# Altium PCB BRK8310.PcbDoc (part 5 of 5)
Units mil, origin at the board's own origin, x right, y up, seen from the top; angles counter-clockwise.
Board outline 6600.39 x 4492.13 mil, 4 copper layers (L1-Top, L2-GND, L3-GND, L4-BOT), stack 60.25 mil thick; 119 components, 266 nets, 1026 pads, 596 vias.
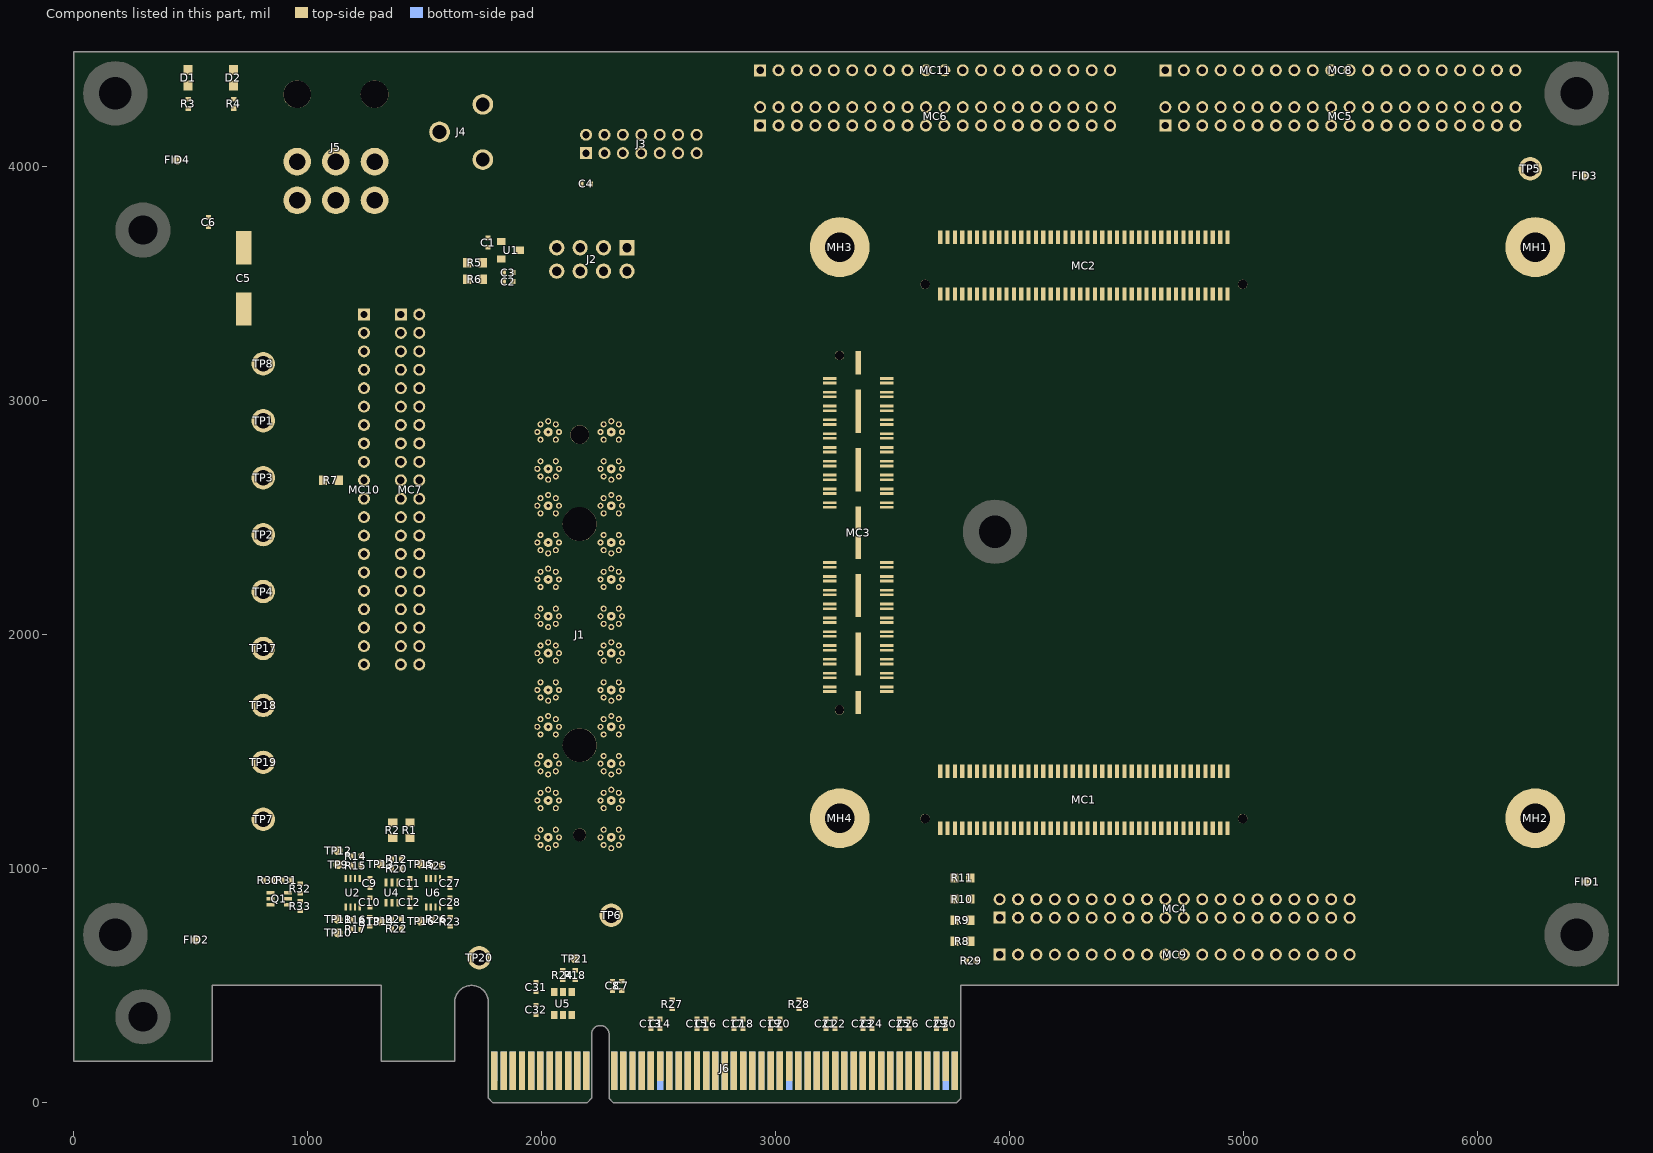
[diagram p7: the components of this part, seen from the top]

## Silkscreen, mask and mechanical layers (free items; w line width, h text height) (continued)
Outline:
  lines w3.94: -0.01,177.16 -0.01,4492.13 6600.39,4492.13 6600.39,501.97 3791.33,501.97 3791.33,19.68 3771.65,0 2307.08,0 2287.39,19.68 2287.39,293.31 ccw(c2249.99,293.31) 2212.59,293.31 2212.59,19.68 2192.91,0 1791.33,0 1771.65,19.68 1771.65,430.12 ccw(c1699.8,430.12) 1627.94,430.12 1627.94,177.16 1312.98,177.16 1312.98,501.97 590.54,501.97 590.54,177.16 -0.01,177.16
  lines w11.81: 6600.39,1059.05 6600.39,3814.96
Fab Notes:
  drawing of 62 lines, arcs and shapes, not listed
  text "LAYER STACKUP TABLE" at 7937.01,7409.45 h80
  text "S" at 12634.42,7288.77 h81.74
  text "i" at 12667.19,7288.77 h81.74
  text "n" at 12685.92,7288.77 h81.74
  text "g" at 12723.37,7288.77 h81.74
  text "l" at 12756.14,7288.77 h81.74
  text "e" at 12774.86,7288.77 h81.74
  text "-" at 12812.31,7288.76 h81.74
  text "D" at 10924.29,7195.14 h81.74
  text "i" at 10966.42,7195.14 h81.74
  text "f" at 10985.14,7195.14 h81.74
  text "f" at 11008.55,7195.14 h81.74
  text "e" at 11031.96,7195.14 h81.74
  text "r" at 11069.41,7195.14 h81.74
  text "e" at 11092.81,7195.14 h81.74
  text "n" at 11130.26,7195.14 h81.74
  text "t" at 11167.71,7195.14 h81.74
  text "i" at 11191.12,7195.14 h81.74
  text "a" at 11209.85,7195.14 h81.74
  text "l" at 11242.62,7195.14 h81.74
  text "D" at 11312.1,7195.14 h81.74
  text "i" at 11354.24,7195.14 h81.74
  text "f" at 11372.96,7195.14 h81.74
  text "f" at 11396.37,7195.14 h81.74
  text "e" at 11419.77,7195.14 h81.74
  text "r" at 11457.22,7195.14 h81.74
  text "e" at 11480.63,7195.14 h81.74
  text "n" at 11518.08,7195.14 h81.74
  text "t" at 11555.53,7195.14 h81.74
  text "i" at 11578.94,7195.14 h81.74
  text "a" at 11597.66,7195.14 h81.74
  text "l" at 11630.43,7195.14 h81.74
  text "D" at 11746.65,7195.14 h81.74
  text "i" at 11788.78,7195.14 h81.74
  text "f" at 11807.5,7195.14 h81.74
  text "f" at 11830.91,7195.14 h81.74
  text "e" at 11854.32,7195.14 h81.74
  text "r" at 11891.77,7195.14 h81.74
  text "e" at 11915.17,7195.14 h81.74
  text "n" at 11952.62,7195.14 h81.74
  text "t" at 11990.07,7195.14 h81.74
  text "i" at 12013.48,7195.14 h81.74
  text "a" at 12032.21,7195.14 h81.74
  text "l" at 12064.98,7195.14 h81.74
  text "D" at 12134.46,7195.14 h81.74
  text "i" at 12176.6,7195.14 h81.74
  text "f" at 12195.32,7195.14 h81.74
  text "f" at 12218.73,7195.14 h81.74
  text "e" at 12242.13,7195.14 h81.74
  text "r" at 12279.58,7195.14 h81.74
  text "e" at 12302.99,7195.14 h81.74
  text "n" at 12340.44,7195.14 h81.74
  text "t" at 12377.89,7195.14 h81.74
  text "i" at 12401.3,7195.14 h81.74
  text "a" at 12420.02,7195.14 h81.74
  text "l" at 12452.79,7195.14 h81.74
  text "E" at 12643.77,7195.14 h81.74
  text "n" at 12676.54,7195.14 h81.74
  text "d" at 12713.99,7195.14 h81.74
  text "e" at 12751.44,7195.14 h81.74
  text "d" at 12788.89,7195.14 h81.74
  text "T" at 11017.74,7101.52 h81.74
  text "r" at 11050.51,7101.52 h81.74
  text "a" at 11073.91,7101.52 h81.74
  text "c" at 11106.68,7101.52 h81.74
  text "e" at 11134.77,7101.52 h81.74
  text "T" at 11405.55,7101.52 h81.74
  text "r" at 11438.32,7101.52 h81.74
  text "a" at 11461.73,7101.52 h81.74
  text "c" at 11494.5,7101.52 h81.74
  text "e" at 11522.59,7101.52 h81.74
  text "T" at 11840.1,7101.52 h81.74
  text "r" at 11872.87,7101.52 h81.74
  text "a" at 11896.27,7101.52 h81.74
  text "c" at 11929.04,7101.52 h81.74
  text "e" at 11957.13,7101.52 h81.74
  text "T" at 12227.91,7101.52 h81.74
  text "r" at 12260.68,7101.52 h81.74
  text "a" at 12284.09,7101.52 h81.74
  text "c" at 12316.86,7101.52 h81.74
  text "e" at 12344.95,7101.52 h81.74
  text "T" at 12657.78,7101.52 h81.74
  text "r" at 12690.55,7101.52 h81.74
  text "a" at 12713.96,7101.52 h81.74
  text "c" at 12746.73,7101.52 h81.74
  text "e" at 12774.82,7101.52 h81.74
  text "S" at 12933.46,7101.52 h81.74
  text "i" at 12966.23,7101.52 h81.74
  text "n" at 12984.96,7101.52 h81.74
  text "g" at 13022.41,7101.52 h81.74
  text "l" at 13055.18,7101.52 h81.74
  text "e" at 13073.9,7101.52 h81.74
  text "-" at 13111.35,7101.51 h81.74
  text "E" at 13134.76,7101.51 h81.74
  text "n" at 13167.53,7101.52 h81.74
  text "d" at 13204.98,7101.52 h81.74
  text "e" at 13242.43,7101.52 h81.74
  text "d" at 13279.88,7101.52 h81.74
  text "M" at 10120.62,7100.13 h77.19
  text "a" at 10172.11,7100.13 h77.19
  text "t" at 10209.56,7100.13 h77.19
  text "e" at 10228.29,7100.13 h77.19
  text "r" at 10265.74,7100.13 h77.19
  text "i" at 10289.14,7100.13 h77.19
  text "a" at 10303.19,7100.13 h77.19
  text "l" at 10340.64,7100.13 h77.19
  text "G" at 8816.99,7011.19 h77.19
  text "e" at 8868.48,7011.19 h77.19
  text "r" at 8905.93,7011.19 h77.19
  text "b" at 8929.34,7011.19 h77.19
  text "e" at 8966.79,7011.19 h77.19
  text "r" at 9004.24,7011.19 h77.19
  text "M" at 9578.61,7011.19 h77.19
  text "a" at 9630.1,7011.19 h77.19
  text "t" at 9667.55,7011.19 h77.19
  text "e" at 9686.28,7011.19 h77.19
  text "r" at 9723.73,7011.19 h77.19
  text "i" at 9747.13,7011.19 h77.19
  text "a" at 9761.18,7011.19 h77.19
  text "l" at 9798.63,7011.19 h77.19
  text "T" at 10078.56,7011.19 h77.19
  text "h" at 10120.7,7011.19 h77.19
  text "i" at 10158.15,7011.19 h77.19
  text "c" at 10172.19,7011.19 h77.19
  text "k" at 10209.64,7011.19 h77.19
  text "n" at 10242.41,7011.19 h77.19
  text "e" at 10279.86,7011.19 h77.19
  text "s" at 10317.31,7011.19 h77.19
  text "s" at 10354.76,7011.19 h77.19
  text "C" at 10541.14,7007.89 h81.74
  text "o" at 10578.59,7007.89 h81.74
  text "p" at 10616.04,7007.89 h81.74
  text "p" at 10653.49,7007.89 h81.74
  text "e" at 10690.94,7007.89 h81.74
  text "r" at 10728.39,7007.89 h81.74
  text "I" at 10933.63,7007.89 h81.74
  text "m" at 10952.36,7007.89 h81.74
  text "p" at 11008.53,7007.89 h81.74
  text "e" at 11045.98,7007.89 h81.74
  text "d" at 11083.43,7007.89 h81.74
  text "a" at 11120.88,7007.89 h81.74
  text "n" at 11153.65,7007.89 h81.74
  text "c" at 11191.1,7007.89 h81.74
  text "e" at 11219.19,7007.89 h81.74
  text "W" at 11293.41,7007.89 h81.74
  text "i" at 11354.27,7007.89 h81.74
  text "d" at 11373,7007.89 h81.74
  text "t" at 11410.45,7007.89 h81.74
  text "h" at 11433.85,7007.89 h81.74
  text "/" at 11471.3,7007.89 h81.74
  text "S" at 11499.39,7007.89 h81.74
  text "p" at 11532.16,7007.89 h81.74
  text "a" at 11569.61,7007.89 h81.74
  text "c" at 11602.38,7007.89 h81.74
  text "e" at 11630.47,7007.89 h81.74
  text "I" at 11755.99,7007.89 h81.74
  text "m" at 11774.72,7007.89 h81.74
  text "p" at 11830.89,7007.89 h81.74
  text "e" at 11868.34,7007.89 h81.74
  text "d" at 11905.79,7007.89 h81.74
  text "a" at 11943.24,7007.89 h81.74
  text "n" at 11976.01,7007.89 h81.74
  text "c" at 12013.46,7007.89 h81.74
  text "e" at 12041.55,7007.89 h81.74
  text "W" at 12115.77,7007.89 h81.74
  text "i" at 12176.63,7007.89 h81.74
  text "d" at 12195.36,7007.89 h81.74
  text "t" at 12232.81,7007.89 h81.74
  text "h" at 12256.21,7007.89 h81.74
  text "/" at 12293.66,7007.89 h81.74
  text "S" at 12321.75,7007.89 h81.74
  text "p" at 12354.52,7007.89 h81.74
  text "a" at 12391.97,7007.89 h81.74
  text "c" at 12424.74,7007.89 h81.74
  text "e" at 12452.83,7007.89 h81.74
  text "I" at 12573.68,7007.89 h81.74
  text "m" at 12592.4,7007.89 h81.74
  text "p" at 12648.58,7007.89 h81.74
  text "e" at 12686.03,7007.89 h81.74
  text "d" at 12723.48,7007.89 h81.74
  text "a" at 12760.93,7007.89 h81.74
  text "n" at 12793.7,7007.89 h81.74
  text "c" at 12831.15,7007.89 h81.74
  text "e" at 12859.24,7007.89 h81.74
  text "T" at 12952.15,7007.89 h81.74
  text "r" at 12984.92,7007.89 h81.74
  text "a" at 13008.33,7007.89 h81.74
  text "c" at 13041.1,7007.89 h81.74
  text "e" at 13069.18,7007.89 h81.74
  text "W" at 13120.68,7007.89 h81.74
  text "i" at 13181.54,7007.89 h81.74
  text "d" at 13200.26,7007.89 h81.74
  text "t" at 13237.71,7007.89 h81.74
  text "h" at 13261.12,7007.89 h81.74
  text "L" at 7919.87,6922.24 h77.19
  text "a" at 7957.32,6922.24 h77.19
  text "y" at 7994.77,6922.23 h77.19
  text "e" at 8027.54,6922.24 h77.19
  text "r" at 8064.99,6922.24 h77.19
  text "L" at 8153.49,6922.24 h77.19
  text "a" at 8190.94,6922.24 h77.19
  text "y" at 8228.4,6922.23 h77.19
  text "e" at 8261.16,6922.24 h77.19
  text "r" at 8298.61,6922.24 h77.19
  text "N" at 8340.75,6922.24 h77.19
  text "a" at 8387.56,6922.24 h77.19
  text "m" at 8425.01,6922.24 h77.19
  text "e" at 8485.87,6922.24 h77.19
  text "L" at 8816.99,6922.24 h77.19
  text "a" at 8854.44,6922.24 h77.19
  text "y" at 8891.89,6922.23 h77.19
  text "e" at 8924.66,6922.24 h77.19
  text "r" at 8962.11,6922.24 h77.19
  text "M" at 9097.34,6922.24 h77.19
  text "a" at 9148.83,6922.24 h77.19
  text "t" at 9186.28,6922.24 h77.19
  text "e" at 9205.01,6922.24 h77.19
  text "r" at 9242.46,6922.24 h77.19
  text "i" at 9265.87,6922.24 h77.19
  text "a" at 9279.91,6922.24 h77.19
  text "l" at 9317.36,6922.24 h77.19
  text "T" at 9350.13,6922.24 h77.19
  text "y" at 9392.26,6922.23 h77.19
  text "p" at 9425.03,6922.24 h77.19
  text "e" at 9462.48,6922.24 h77.19
  text "C" at 9578.61,6922.24 h77.19
  text "o" at 9630.1,6922.24 h77.19
  text "n" at 9667.55,6922.24 h77.19
  text "s" at 9705,6922.24 h77.19
  text "t" at 9742.45,6922.24 h77.19
  text "r" at 9761.18,6922.24 h77.19
  text "u" at 9784.58,6922.24 h77.19
  text "c" at 9822.03,6922.24 h77.19
  text "t" at 9859.48,6922.24 h77.19
  text "i" at 9878.21,6922.24 h77.19
  text "o" at 9892.25,6922.24 h77.19
  text "n" at 9929.7,6922.24 h77.19
  text "(" at 10153.32,6922.23 h77.19
  text "m" at 10176.73,6922.24 h77.19
  text "m" at 10237.59,6922.24 h77.19
  text ")" at 10298.44,6922.23 h77.19
  text "W" at 10475.73,6914.26 h81.74
  text "e" at 10536.58,6914.26 h81.74
  text "i" at 10574.03,6914.26 h81.74
  text "g" at 10592.76,6914.27 h81.74
  text "h" at 10625.53,6914.26 h81.74
  text "t" at 10662.98,6914.26 h81.74
  text "(" at 10700.43,6914.27 h81.74
  text "o" at 10723.84,6914.26 h81.74
  text "z" at 10761.29,6914.26 h81.74
  text ")" at 10789.37,6914.27 h81.74
  text "(" at 10989.7,6914.27 h81.74
  text "o" at 11013.11,6914.26 h81.74
  text "h" at 11050.56,6914.26 h81.74
  text "m" at 11088.01,6914.26 h81.74
  text "s" at 11144.18,6914.26 h81.74
  text ")" at 11172.27,6914.27 h81.74
  text "(" at 11396.21,6914.27 h81.74
  text "m" at 11419.62,6914.26 h81.74
  text "i" at 11475.79,6914.26 h81.74
  text "l" at 11494.52,6914.26 h81.74
  text "s" at 11513.24,6914.26 h81.74
  text ")" at 11541.33,6914.27 h81.74
  text "(" at 11812.06,6914.27 h81.74
  text "o" at 11835.47,6914.26 h81.74
  text "h" at 11872.92,6914.26 h81.74
  text "m" at 11910.37,6914.26 h81.74
  text "s" at 11966.54,6914.26 h81.74
  text ")" at 11994.63,6914.27 h81.74
  text "(" at 12218.57,6914.27 h81.74
  text "m" at 12241.98,6914.26 h81.74
  text "i" at 12298.15,6914.26 h81.74
  text "l" at 12316.88,6914.26 h81.74
  text "s" at 12335.6,6914.26 h81.74
  text ")" at 12363.69,6914.27 h81.74
  text "(" at 12634.42,6914.27 h81.74
  text "o" at 12657.83,6914.26 h81.74
  text "h" at 12695.28,6914.26 h81.74
  text "m" at 12732.73,6914.26 h81.74
  text "s" at 12788.9,6914.26 h81.74
  text ")" at 12816.99,6914.27 h81.74
  text "(" at 13040.93,6914.27 h81.74
  text "m" at 13064.34,6914.26 h81.74
  text "i" at 13120.51,6914.26 h81.74
  text "l" at 13139.24,6914.26 h81.74
  text "s" at 13157.96,6914.26 h81.74
  text ")" at 13186.05,6914.27 h81.74
  text "O" at 8153.49,6781.81 h77.19
  text "v" at 8209.67,6781.81 h77.19
  text "e" at 8242.44,6781.81 h77.19
  text "r" at 8279.89,6781.81 h77.19
  text "l" at 8303.3,6781.81 h77.19
  text "a" at 8317.34,6781.81 h77.19
  text "y" at 8354.79,6781.8 h77.19
  text "T" at 8406.28,6781.81 h77.19
  text "o" at 8448.42,6781.81 h77.19
  text "p" at 8485.87,6781.8 h77.19
  text "G" at 8816.99,6781.81 h77.19
  text "T" at 8868.48,6781.81 h77.19
  text "O" at 8910.62,6781.81 h77.19
  text "S" at 9097.34,6781.81 h77.19
  text "i" at 9144.15,6781.81 h77.19
  text "l" at 9158.2,6781.81 h77.19
  text "k" at 9172.24,6781.81 h77.19
  text "s" at 9205.01,6781.81 h77.19
  text "c" at 9242.46,6781.81 h77.19
  text "r" at 9279.91,6781.81 h77.19
  text "e" at 9303.32,6781.81 h77.19
  text "e" at 9340.77,6781.81 h77.19
  text "n" at 9378.22,6781.81 h77.19
  text "S" at 8153.49,6688.18 h77.19
  text "o" at 8200.31,6688.18 h77.19
  text "l" at 8237.76,6688.18 h77.19
  text "d" at 8251.8,6688.18 h77.19
  text "e" at 8289.25,6688.18 h77.19
  text "r" at 8326.7,6688.18 h77.19
  text "M" at 8368.83,6688.18 h77.19
  text "a" at 8420.33,6688.18 h77.19
  text "s" at 8457.78,6688.18 h77.19
  text "k" at 8495.23,6688.18 h77.19
  text "T" at 8546.72,6688.18 h77.19
  text "o" at 8588.86,6688.18 h77.19
  text "p" at 8626.31,6688.17 h77.19
  text "G" at 8816.99,6688.18 h77.19
  text "T" at 8868.48,6688.18 h77.19
  text "S" at 8910.62,6688.18 h77.19
  text "S" at 9097.34,6688.18 h77.19
  text "o" at 9144.15,6688.18 h77.19
  text "l" at 9181.6,6688.18 h77.19
  text "d" at 9195.65,6688.18 h77.19
  text "e" at 9233.1,6688.18 h77.19
  text "r" at 9270.55,6688.18 h77.19
  text "R" at 9312.68,6688.18 h77.19
  text "e" at 9364.17,6688.18 h77.19
  text "s" at 9401.62,6688.18 h77.19
  text "i" at 9439.07,6688.18 h77.19
  text "s" at 9453.12,6688.18 h77.19
  text "t" at 9490.57,6688.18 h77.19
  text "1" at 7919.87,6594.55 h77.19
  text "L" at 8153.49,6594.55 h77.19
  text "1" at 8190.94,6594.55 h77.19
  text "-" at 8228.4,6594.56 h77.19
  text "T" at 8251.8,6594.55 h77.19
  text "O" at 8293.93,6594.55 h77.19
  text "P" at 8350.11,6594.55 h77.19
  text "G" at 8816.99,6594.55 h77.19
  text "T" at 8868.48,6594.55 h77.19
  text "L" at 8910.62,6594.55 h77.19
  text "C" at 9097.34,6594.55 h77.19
  text "o" at 9148.83,6594.55 h77.19
  text "p" at 9186.28,6594.54 h77.19
  text "p" at 9223.73,6594.54 h77.19
  text "e" at 9261.18,6594.55 h77.19
  text "r" at 9298.64,6594.55 h77.19
  text "0" at 10471.05,6591.25 h81.74
  text "." at 10503.82,6591.25 h81.74
  text "5" at 10522.55,6591.25 h81.74
  text "+" at 10569.36,6591.25 h81.74
  text "p" at 10616.17,6591.26 h81.74
  text "l" at 10653.62,6591.25 h81.74
  text "a" at 10672.35,6591.25 h81.74
  text "t" at 10705.12,6591.25 h81.74
  text "i" at 10728.53,6591.25 h81.74
  text "n" at 10747.25,6591.25 h81.74
  text "g" at 10784.7,6591.26 h81.74
  text "8" at 11059.79,6591.25 h81.74
  text "5" at 11092.56,6591.25 h81.74
  text "7" at 11335.47,6591.25 h81.74
  text "." at 11368.24,6591.25 h81.74
  text "5" at 11386.96,6591.25 h81.74
  text "0" at 11419.73,6591.25 h81.74
  text "/" at 11466.54,6591.26 h81.74
  text "6" at 11508.67,6591.25 h81.74
  text "." at 11541.44,6591.25 h81.74
  text "0" at 11560.17,6591.25 h81.74
  text "0" at 11592.94,6591.25 h81.74
  text "1" at 11868.13,6591.25 h81.74
  text "0" at 11900.9,6591.25 h81.74
  text "0" at 11933.67,6591.25 h81.74
  text "5" at 12157.83,6591.25 h81.74
  text "." at 12190.6,6591.25 h81.74
  text "2" at 12209.32,6591.25 h81.74
  text "5" at 12242.09,6591.25 h81.74
  text "/" at 12288.9,6591.26 h81.74
  text "6" at 12331.03,6591.25 h81.74
  text "." at 12363.8,6591.25 h81.74
  text "0" at 12382.53,6591.25 h81.74
  text "0" at 12415.3,6591.25 h81.74
  text "5" at 12704.51,6591.25 h81.74
  text "0" at 12737.28,6591.25 h81.74
  text "7" at 13082.98,6591.25 h81.74
  text "." at 13115.75,6591.25 h81.74
  text "5" at 13134.48,6591.25 h81.74
  text "P" at 9097.34,6500.93 h77.19
  text "r" at 9144.15,6500.93 h77.19
  text "e" at 9167.56,6500.93 h77.19
  text "p" at 9205.01,6500.92 h77.19
  text "r" at 9242.46,6500.93 h77.19
  text "e" at 9265.87,6500.93 h77.19
  text "g" at 9303.32,6500.92 h77.19
  text "S" at 9578.61,6497.63 h81.74
  text "1" at 9611.38,6497.63 h81.74
  text "0" at 9644.15,6497.63 h81.74
  text "0" at 9676.91,6497.63 h81.74
  text "0" at 9709.68,6497.63 h81.74
  text "-" at 9742.45,6497.62 h81.74
  text "2" at 9765.86,6497.63 h81.74
  text "M" at 9798.63,6497.63 h81.74
  text "0" at 10162.67,6497.63 h81.74
  text "." at 10195.44,6497.63 h81.74
  text "1" at 10214.16,6497.63 h81.74
  text "2" at 10246.93,6497.63 h81.74
  text "3" at 10279.7,6497.63 h81.74
  text "2" at 7919.87,6407.3 h77.19
  text "L" at 8153.49,6407.3 h77.19
  text "2" at 8190.94,6407.3 h77.19
  text "-" at 8228.4,6407.31 h77.19
  text "G" at 8251.8,6407.3 h77.19
  text "N" at 8303.3,6407.3 h77.19
  text "D" at 8350.11,6407.3 h77.19
  text "G" at 8816.99,6407.3 h77.19
  text "1" at 8868.48,6407.3 h77.19
  text "C" at 9097.34,6407.3 h77.19
  text "o" at 9148.83,6407.3 h77.19
  text "p" at 9186.28,6407.29 h77.19
  text "p" at 9223.73,6407.29 h77.19
  text "e" at 9261.18,6407.3 h77.19
  text "r" at 9298.64,6407.3 h77.19
  text "1" at 10629.92,6404 h81.74
  text "C" at 9097.34,6313.68 h77.19
  text "o" at 9148.83,6313.68 h77.19
  text "r" at 9186.28,6313.68 h77.19
  text "e" at 9209.69,6313.68 h77.19
  text "1" at 10162.67,6310.38 h81.74
  text "." at 10195.44,6310.38 h81.74
  text "1" at 10214.16,6310.38 h81.74
  text "4" at 10246.93,6310.38 h81.74
  text "3" at 10279.7,6310.38 h81.74
  text "3" at 7919.87,6220.05 h77.19
  text "L" at 8153.49,6220.05 h77.19
  text "3" at 8190.94,6220.05 h77.19
  text "-" at 8228.4,6220.06 h77.19
  text "P" at 8251.8,6220.05 h77.19
  text "W" at 8298.61,6220.05 h77.19
  text "R" at 8368.83,6220.05 h77.19
  text "G" at 8816.99,6220.05 h77.19
  text "2" at 8868.48,6220.05 h77.19
  text "C" at 9097.34,6220.05 h77.19
  text "o" at 9148.83,6220.05 h77.19
  text "p" at 9186.28,6220.04 h77.19
  text "p" at 9223.73,6220.04 h77.19
  text "e" at 9261.18,6220.05 h77.19
  text "r" at 9298.64,6220.05 h77.19
  text "1" at 10629.92,6216.75 h81.74
  text "P" at 9097.34,6126.42 h77.19
  text "r" at 9144.15,6126.42 h77.19
  text "e" at 9167.56,6126.42 h77.19
  text "p" at 9205.01,6126.41 h77.19
  text "r" at 9242.46,6126.42 h77.19
  text "e" at 9265.87,6126.42 h77.19
  text "g" at 9303.32,6126.41 h77.19
  text "S" at 9578.61,6123.12 h81.74
  text "1" at 9611.38,6123.12 h81.74
  text "0" at 9644.15,6123.12 h81.74
  text "0" at 9676.91,6123.12 h81.74
  text "0" at 9709.68,6123.12 h81.74
  text "-" at 9742.45,6123.12 h81.74
  text "2" at 9765.86,6123.12 h81.74
  text "M" at 9798.63,6123.12 h81.74
  text "0" at 10162.67,6123.12 h81.74
  text "." at 10195.44,6123.12 h81.74
  text "1" at 10214.16,6123.12 h81.74
  text "2" at 10246.93,6123.12 h81.74
  text "3" at 10279.7,6123.12 h81.74
  text "4" at 7919.87,6032.8 h77.19
  text "L" at 8153.49,6032.8 h77.19
  text "4" at 8190.94,6032.8 h77.19
  text "-" at 8228.4,6032.81 h77.19
  text "B" at 8251.8,6032.8 h77.19
  text "O" at 8298.61,6032.8 h77.19
  text "T" at 8354.79,6032.8 h77.19
  text "G" at 8816.99,6032.8 h77.19
  text "B" at 8868.48,6032.8 h77.19
  text "L" at 8915.3,6032.8 h77.19
  text "C" at 9097.34,6032.8 h77.19
  text "o" at 9148.83,6032.8 h77.19
  text "p" at 9186.28,6032.79 h77.19
  text "p" at 9223.73,6032.79 h77.19
  text "e" at 9261.18,6032.8 h77.19
  text "r" at 9298.64,6032.8 h77.19
  text "p" at 10616.17,6029.5 h81.74
  text "g" at 10784.7,6029.5 h81.74
  text "/" at 11466.54,6029.5 h81.74
  text "/" at 12288.9,6029.5 h81.74
  text "0" at 10471.05,6029.5 h81.74
  text "." at 10503.82,6029.5 h81.74
  text "5" at 10522.55,6029.5 h81.74
  text "+" at 10569.36,6029.5 h81.74
  text "l" at 10653.62,6029.5 h81.74
  text "a" at 10672.35,6029.5 h81.74
  text "t" at 10705.12,6029.5 h81.74
  text "i" at 10728.53,6029.5 h81.74
  text "n" at 10747.25,6029.5 h81.74
  text "8" at 11059.79,6029.5 h81.74
  text "5" at 11092.56,6029.5 h81.74
  text "7" at 11335.47,6029.5 h81.74
  text "." at 11368.24,6029.5 h81.74
  text "5" at 11386.96,6029.5 h81.74
  text "0" at 11419.73,6029.5 h81.74
  text "6" at 11508.67,6029.5 h81.74
  text "." at 11541.44,6029.5 h81.74
  text "0" at 11560.17,6029.5 h81.74
  text "0" at 11592.94,6029.5 h81.74
  text "1" at 11868.13,6029.5 h81.74
  text "0" at 11900.9,6029.5 h81.74
  text "0" at 11933.67,6029.5 h81.74
  text "5" at 12157.83,6029.5 h81.74
  text "." at 12190.6,6029.5 h81.74
  text "2" at 12209.32,6029.5 h81.74
  text "5" at 12242.09,6029.5 h81.74
  text "6" at 12331.03,6029.5 h81.74
  text "." at 12363.8,6029.5 h81.74
  text "0" at 12382.53,6029.5 h81.74
  text "0" at 12415.3,6029.5 h81.74
  text "5" at 12704.51,6029.5 h81.74
  text "0" at 12737.28,6029.5 h81.74
  text "7" at 13082.98,6029.5 h81.74
  text "." at 13115.75,6029.5 h81.74
  text "5" at 13134.48,6029.5 h81.74
  text "S" at 8153.49,5939.17 h77.19
  text "o" at 8200.31,5939.17 h77.19
  text "l" at 8237.76,5939.17 h77.19
  text "d" at 8251.8,5939.17 h77.19
  text "e" at 8289.25,5939.17 h77.19
  text "r" at 8326.7,5939.17 h77.19
  text "M" at 8368.83,5939.17 h77.19
  text "a" at 8420.33,5939.17 h77.19
  text "s" at 8457.78,5939.17 h77.19
  text "k" at 8495.23,5939.17 h77.19
  text "B" at 8546.72,5939.17 h77.19
  text "o" at 8593.54,5939.17 h77.19
  text "t" at 8630.99,5939.17 h77.19
  text "t" at 8649.71,5939.17 h77.19
  text "o" at 8668.44,5939.17 h77.19
  text "m" at 8705.89,5939.17 h77.19
  text "G" at 8816.99,5939.17 h77.19
  text "B" at 8868.48,5939.17 h77.19
  text "S" at 8915.3,5939.17 h77.19
  text "S" at 9097.34,5939.17 h77.19
  text "o" at 9144.15,5939.17 h77.19
  text "l" at 9181.6,5939.17 h77.19
  text "d" at 9195.65,5939.17 h77.19
  text "e" at 9233.1,5939.17 h77.19
  text "r" at 9270.55,5939.17 h77.19
  text "R" at 9312.68,5939.17 h77.19
  text "e" at 9364.17,5939.17 h77.19
  text "s" at 9401.62,5939.17 h77.19
  text "i" at 9439.07,5939.17 h77.19
  text "s" at 9453.12,5939.17 h77.19
  text "t" at 9490.57,5939.17 h77.19
  text "O" at 8153.49,5845.55 h77.19
  text "v" at 8209.67,5845.55 h77.19
  text "e" at 8242.44,5845.55 h77.19
  text "r" at 8279.89,5845.55 h77.19
  text "l" at 8303.3,5845.55 h77.19
  text "a" at 8317.34,5845.55 h77.19
  text "y" at 8354.79,5845.54 h77.19
  text "B" at 8406.28,5845.55 h77.19
  text "o" at 8453.1,5845.55 h77.19
  text "t" at 8490.55,5845.55 h77.19
  text "t" at 8509.27,5845.55 h77.19
  text "o" at 8528,5845.55 h77.19
  text "m" at 8565.45,5845.55 h77.19
  text "G" at 8816.99,5845.55 h77.19
  text "B" at 8868.48,5845.55 h77.19
  text "O" at 8915.3,5845.55 h77.19
  text "S" at 9097.34,5845.55 h77.19
  text "i" at 9144.15,5845.55 h77.19
  text "l" at 9158.2,5845.55 h77.19
  text "k" at 9172.24,5845.55 h77.19
  text "s" at 9205.01,5845.55 h77.19
  text "c" at 9242.46,5845.55 h77.19
  text "r" at 9279.91,5845.55 h77.19
  text "e" at 9303.32,5845.55 h77.19
  text "e" at 9340.77,5845.55 h77.19
  text "n" at 9378.22,5845.55 h77.19
  text "NOTES: /  / 1. MATERIAL: /    FR408 or equivalent /    Surface finish: ENIG /    Overall thickness: 62 mils +/-10% /  / 2. Fabricate to IPC-6012 (latest revision), Class 2 /  / 3. SOLDER RESIST: Blue LPI applied over bare copper or gold/nickel plating /  / 4. SILKSCREEN: White /  / 5. All vendor markings must be on bottom side of PCB /  / 6. LOT CODE IDENTIFICATION: /    Supplier must add identifier and lot code date to silkscreen. /    LOT CODE DATE FORMAT: YYWW (YY = 2-digit year, WW = 2-digit week) /  / 7. Drill sizes are finished size after plating /  / 8. 100% electrical bare board test required for continuity /  / 9. IMPEDANCE CONTROL: /    See Layer Stackup Table on this drawing and refer to '.Part_Number'-PCBStackup.pdf /  / 10. PANELIZATION: /    2 pieces per array /    Tab routing required. Tab locations indicated by ::: (see Dimensions Gerber layer) /    OUTLINE DIMENSION TOLERANCE: +/-0.127 mm /    0.25-inch rails on all sides /  / 11. POFV: All 10-mil diameter vias must be filled using non-conductive epoxy and plated over. /  / 12. ROHS: Fabricate to meet EU RoHS directive. Supplier must add lead-free marking in silkscreen. /  / 13. UL: Supplier must add UL certification marking (94V-0) in silkscreen. /  / 14. Remove all non-functional pads from internal layers /  / 15. PCIE fingers must be plated with 30 micro inches of hard gold" at 9059.06,3051.18 h38
Mechanical 7:
  lines w3.94: -0.01,177.16 -0.01,541.34 1771.65,541.34 1771.65,430.12 ccw(c1699.8,430.12) 1627.94,430.12 1627.94,312.99 1312.98,312.99 1312.98,501.97 590.54,501.97 590.54,177.16 -0.01,177.16
Drill Drawing:
  circle w8: c8618.36,-508.51 r16.67
  circle w8: c8618.36,-508.51 r27.78
  lines w8: 8590.58,-661.29 8618.36,-647.4 8646.14,-661.29 8632.25,-633.51 8646.14,-605.74 8618.36,-619.62 8590.58,-605.74 8604.47,-633.51 8590.58,-661.29 ; 8590.58,-411.29 8618.36,-397.4 8646.14,-411.29 8632.25,-383.51 8646.14,-355.74 8618.36,-369.62 8590.58,-355.74 8604.47,-383.51 8590.58,-411.29 ; 8590.58,-272.4 8604.47,-272.4 8618.36,-286.29 8632.25,-272.4 8646.14,-272.4 8632.25,-258.51 8646.14,-244.62 8632.25,-244.62 8618.36,-230.74 8604.47,-244.62 8590.58,-244.62 8604.47,-258.51 8590.58,-272.4 ; 8590.58,-36.29 8646.14,-36.29 8646.14,19.26 8590.58,19.26 8590.58,-36.29 ; 8590.58,241.49 8618.36,213.71 8646.14,241.49 8618.36,269.26 8590.58,241.49 ; 8590.58,338.71 8646.14,338.71 8646.14,394.26 8590.58,394.26 8590.58,338.71 ; 8590.58,519.26 8646.14,519.26 8618.36,463.71 8590.58,519.26 ; 8590.58,602.6 8604.47,602.6 8604.47,588.71 8632.25,588.71 8632.25,602.6 8646.14,602.6 8646.14,630.38 8632.25,630.38 8632.25,644.26 8604.47,644.26 8604.47,630.38 8590.58,630.38 8590.58,602.6 ; 8590.58,1019.26 8646.14,1019.26 8618.36,963.71 8590.58,1019.26 ; 8590.58,1088.71 8590.58,1102.6 8604.47,1116.49 8590.58,1130.38 8590.58,1144.26 8604.47,1144.26 8618.36,1130.38 8632.25,1144.26 8646.14,1144.26 8646.14,1130.38 8632.25,1116.49 8646.14,1102.6 8646.14,1088.71 8632.25,1088.71 8618.36,1102.6 8604.47,1088.71 8590.58,1088.71 ; 8601.69,-650.18 8618.36,-641.85 8635.03,-650.18 8626.69,-633.51 8635.03,-616.85 8618.36,-625.18 8601.69,-616.85 8610.03,-633.51 8601.69,-650.18 ; 8601.69,-266.85 8610.03,-266.85 8618.36,-275.18 8626.69,-266.85 8635.03,-266.85 8626.69,-258.51 8635.03,-250.18 8626.69,-250.18 8618.36,-241.85 8610.03,-250.18 8601.69,-250.18 8610.03,-258.51 8601.69,-266.85 ; 8601.69,-25.18 8635.03,-25.18 8635.03,8.15 8601.69,8.15 8601.69,-25.18 ; 8601.69,508.15 8635.03,508.15 8618.36,474.82 8601.69,508.15
  lines w10: 8540.86,-698.79 13336.22,-698.79 ; 8540.86,1176.21 13336.22,1176.21 ; 8998.86,-823.79 8998.86,1301.21 ; 9539.71,-823.79 9539.71,1301.21 ; 10497.1,-823.79 10497.1,1301.21 ; 10917.59,-823.79 10917.59,1301.21 ; 11907.91,-823.79 11907.91,1301.21 ; 12398.38,-823.79 12398.38,1301.21 ; 8540.86,-823.79 13336.22,-823.79 13336.22,1301.21 8540.86,1301.21 8540.86,-823.79
  text "DRILL TABLE" at 8599.41,1337.6 h50
  text "Symbol" at 8615.86,1213.71 h60
  text "Count" at 9036.36,1213.71 h60
  text "Hole Size" at 9577.21,1213.71 h60
  text "Plated" at 10534.6,1213.71 h60
  text "Drill Layer Pair" at 10955.09,1213.71 h60
  text "Via/Pad" at 11945.41,1213.71 h60
  text "Hole Tolerance" at 12435.88,1213.71 h60
  text "596" at 9036.36,1088.71 h50
  text "10.00mil (0.254mm)" at 9577.21,1088.71 h50
  text "PTH" at 10534.6,1088.71 h50
  text "L1-Top - L4-BOT" at 10955.09,1088.71 h50
  text "Via" at 11945.41,1088.71 h50
  text "+/-3.00mil" at 12435.88,1088.71 h50
  text "192" at 9036.36,963.71 h50
  text "14.17mil (0.360mm)" at 9577.21,963.71 h50
  text "PTH" at 10534.6,963.71 h50
  text "L1-Top - L4-BOT" at 10955.09,963.71 h50
  text "Pad" at 11945.41,963.71 h50
  text "+/-3.00mil" at 12435.88,963.71 h50
  text "254" at 9036.36,838.71 h50
  text "31.50mil (0.800mm)" at 9577.21,838.71 h50
  text "PTH" at 10534.6,838.71 h50
  text "L1-Top - L4-BOT" at 10955.09,838.71 h50
  text "Pad" at 11945.41,838.71 h50
  text "+/-3.15mil" at 12435.88,838.71 h50
  text "F" at 8591.85,830.72 h55.56
  text "8" at 9036.36,713.71 h50
  text "40.00mil (1.016mm)" at 9577.21,713.71 h50
  text "PTH" at 10534.6,713.71 h50
  text "L1-Top - L4-BOT" at 10955.09,713.71 h50
  text "Pad" at 11945.41,713.71 h50
  text "+/-3.00mil" at 12435.88,713.71 h50
  text "I" at 8601.11,705.72 h55.56
  text "6" at 9036.36,588.71 h50
  text "40.16mil (1.020mm)" at 9577.21,588.71 h50
  text "NPTH" at 10534.6,588.71 h50
  text "L1-Top - L4-BOT" at 10955.09,588.71 h50
  text "Pad" at 11945.41,588.71 h50
  text "+/-3.00mil" at 12435.88,588.71 h50
  text "1" at 9036.36,463.71 h50
  text "55.12mil (1.400mm)" at 9577.21,463.71 h50
  text "NPTH" at 10534.6,463.71 h50
  text "L1-Top - L4-BOT" at 10955.09,463.71 h50
  text "Pad" at 11945.41,463.71 h50
  text "+/-3.00mil" at 12435.88,463.71 h50
  text "3" at 9036.36,338.71 h50
  text "59.06mil (1.500mm)" at 9577.21,338.71 h50
  text "PTH" at 10534.6,338.71 h50
  text "L1-Top - L4-BOT" at 10955.09,338.71 h50
  text "Pad" at 11945.41,338.71 h50
  text "+/-3.00mil" at 12435.88,338.71 h50
  text "12" at 9036.36,213.71 h50
  text "65.00mil (1.651mm)" at 9577.21,213.71 h50
  text "PTH" at 10534.6,213.71 h50
  text "L1-Top - L4-BOT" at 10955.09,213.71 h50
  text "Pad" at 11945.41,213.71 h50
  text "+/-3.00mil" at 12435.88,213.71 h50
  text "6" at 9036.36,88.71 h50
  text "70.87mil (1.800mm)" at 9577.21,88.71 h50
  text "PTH" at 10534.6,88.71 h50
  text "L1-Top - L4-BOT" at 10955.09,88.71 h50
  text "Pad" at 11945.41,88.71 h50
  text "+/-3.00mil" at 12435.88,88.71 h50
  text "K" at 8591.85,80.72 h55.56
  text "1" at 9036.36,-36.29 h50
  text "79.92mil (2.030mm)" at 9577.21,-36.29 h50
  text "NPTH" at 10534.6,-36.29 h50
  text "L1-Top - L4-BOT" at 10955.09,-36.29 h50
  text "Pad" at 11945.41,-36.29 h50
  text "+/-3.00mil" at 12435.88,-36.29 h50
  text "2" at 9036.36,-161.29 h50
  text "118.11mil (3.000mm)" at 9577.21,-161.29 h50
  text "NPTH" at 10534.6,-161.29 h50
  text "L1-Top - L4-BOT" at 10955.09,-161.29 h50
  text "Pad" at 11945.41,-161.29 h50
  text "+/-3.00mil" at 12435.88,-161.29 h50
  text "J" at 8591.85,-169.28 h55.56
  text "2" at 9036.36,-286.29 h50
  text "125.20mil (3.180mm)" at 9577.21,-286.29 h50
  text "PTH" at 10534.6,-286.29 h50
  text "L1-Top - L4-BOT" at 10955.09,-286.29 h50
  text "Pad" at 11945.41,-286.29 h50
  text "+/-3.00mil" at 12435.88,-286.29 h50
  text "4" at 9036.36,-411.29 h50
  text "125.98mil (3.200mm)" at 9577.21,-411.29 h50
  text "PTH" at 10534.6,-411.29 h50
  text "L1-Top - L4-BOT" at 10955.09,-411.29 h50
  text "Pad" at 11945.41,-411.29 h50
  text "+/-3.00mil" at 12435.88,-411.29 h50
  text "5" at 9036.36,-536.29 h50
  text "137.79mil (3.500mm)" at 9577.21,-536.29 h50
  text "PTH" at 10534.6,-536.29 h50
  text "L1-Top - L4-BOT" at 10955.09,-536.29 h50
  text "Pad" at 11945.41,-536.29 h50
  text "+/-3.00mil" at 12435.88,-536.29 h50
  text "2" at 9036.36,-661.29 h50
  text "144.88mil (3.680mm)" at 9577.21,-661.29 h50
  text "NPTH" at 10534.6,-661.29 h50
  text "L1-Top - L4-BOT" at 10955.09,-661.29 h50
  text "Pad" at 11945.41,-661.29 h50
  text "+/-3.00mil" at 12435.88,-661.29 h50
  text "1094 Total" at 9036.36,-786.29 h50
Doc-Assy-Top:
  lines w5.2: 5124.12,-2166.68 5124.12,-1424.52 8243.15,-1424.52 ; 5124.12,-1916.22 8243.15,-1916.22 ; 5594.81,-2166.68 5594.81,-1916.22 ; 6325.07,-2166.68 6325.07,-1916.22 ; 6471.08,-1915.91 6471.08,-1424.52 ; 7404.58,-2166.68 7404.58,-1916.22
  lines w5.21: -2584.85,-370.83 -2376.61,-370.83 ; -2584.85,1841.8 -2376.61,1841.8 ; -2584.85,4054.43 -2376.61,4054.43 ; 70.3,-2375.21 70.3,-2166.96 ; 70.3,5850.56 70.3,6058.81 ; 2933.7,-2375.21 2933.7,-2166.96 ; 2933.7,5850.56 2933.7,6058.81 ; 3766.69,-2375.21 8452.25,-2375.21 ; 5797.1,-2375.21 5797.1,-2166.96 ; 5797.1,5850.56 5797.1,6058.81 ; 8244.01,-370.83 8452.25,-370.83 ; 8244.01,1841.8 8452.25,1841.8 ; 8244.01,4054.43 8452.25,4054.43 ; 8452.25,-2375.21 -2584.85,-2375.21 -2584.85,6058.81 8452.25,6058.81 8452.25,-2375.21 ; -2376.61,-2166.96 8244.01,-2166.96 8244.01,5850.56 -2376.61,5850.56 -2376.61,-2166.96
  text "1" at -1386.04,5921.52 h72.89
  text "2" at 1478.05,5921.52 h72.89
  text "3" at 4336.25,5921.52 h72.89
  text "4" at 7200.7,5921.52 h72.89
  text "A" at -2510.04,5066.51 h72.89
  text "A" at 8325.38,5066.51 h72.89
  text "B" at -2510.04,2853.88 h72.89
  text "B" at 8325.38,2853.88 h72.89
  text "C" at -2510.04,641.25 h72.89
  text "C" at 8325.38,641.25 h72.89
  text "TITLE:" at 5204.95,-1506.47 h46.83
  text "Opal Kelly" at 6553.03,-1539.25 h72.85
  text "D" at -2510.04,-1566.17 h72.89
  text "D" at 8325.38,-1566.17 h72.89
  text "13500 SW 72nd Ave Suite 100" at 6553.03,-1662.18 h72.85
  text "Portland, OR 97223" at 6553.03,-1764.62 h72.85
  text "'.Part_Number' / Assembly Drawing" at 5238.64,-1766.37 h72.85
  text "www.opalkelly.com" at 6553.03,-1867.05 h72.85
  text "(Top)" at 5238.64,-1885.02 h72.85
  text "REV:" at 5182.05,-1985.62 h46.83
  text "SIZE:" at 5658.31,-1985.62 h46.83
  text "ENGINEER:" at 6388.57,-1985.62 h46.83
  text "DATE:" at 7468.09,-1985.62 h46.83
  text "'.PCB_Revision'XX" at 5245.55,-2112.62 h72.85
  text "ANSI A" at 5721.81,-2112.62 h72.85
  text "RCA" at 6452.07,-2112.62 h72.85
  text ".PRINT_DATE" at 7531.59,-2112.62 h72.85
  text "1" at -1386.04,-2310.81 h72.89
  text "2" at 1478.05,-2310.81 h72.89
  text "3" at 4336.25,-2310.81 h72.89
  text "4" at 7200.7,-2310.81 h72.89
Doc-Assy-Bot:
  lines w5.2: -2376.76,-1915.24 742.64,-1915.24 ; -2376.76,-1423.48 742.64,-1423.48 742.64,-2165.72 ; -1538.1,-2165.72 -1538.1,-1915.24 ; -604.48,-1914.93 -604.48,-1423.48 ; -458.46,-2165.72 -458.46,-1915.24 ; 271.89,-2165.72 271.89,-1915.24
  lines w5.21: -2585.9,-369.66 -2377.63,-369.66 ; -2585.9,1843.24 -2377.63,1843.24 ; -2585.9,4056.13 -2377.63,4056.13 ; 69.58,-2374.28 69.58,-2166.01 ; 69.58,5852.48 69.58,6060.76 ; 2100.23,-2374.28 -2585.9,-2374.28 ; 2933.32,-2374.28 2933.32,-2166.01 ; 2933.32,5852.48 2933.32,6060.76 ; 5797.07,-2374.28 5797.07,-2166.01 ; 5797.07,5852.48 5797.07,6060.76 ; 8244.27,-369.66 8452.54,-369.66 ; 8244.27,1843.24 8452.54,1843.24 ; 8244.27,4056.13 8452.54,4056.13 ; -2585.9,-2374.28 -2585.9,6060.76 8452.54,6060.76 8452.54,-2374.28 -2585.9,-2374.28 ; -2377.63,-2166.01 -2377.63,5852.48 8244.27,5852.48 8244.27,-2166.01 -2377.63,-2166.01
  text "4" at -1334.19,5923.45 h72.9
  text "3" at 1530.61,5923.45 h72.9
  text "2" at 4389.15,5923.45 h72.9
  text "1" at 7253.58,5923.45 h72.9
  text "A" at -2459.01,5068.34 h72.9
  text "A" at 8377.72,5068.34 h72.9
  text "B" at -2459.01,2855.44 h72.9
  text "B" at 8377.72,2855.44 h72.9
  text "C" at -2459.01,642.55 h72.9
  text "C" at 8377.72,642.55 h72.9
  text "TITLE:" at 661.8,-1505.44 h46.84
  text "Opal Kelly" at -686.44,-1538.22 h72.86
  text "D" at -2459.01,-1565.14 h72.9
  text "D" at 8377.72,-1565.14 h72.9
  text "13500 SW 72nd Ave Suite 100" at -686.44,-1661.16 h72.86
  text "Portland, OR 97223" at -686.44,-1763.61 h72.86
  text "'.Part_Number' / Assembly Drawing" at 628.11,-1765.37 h72.86
  text "www.opalkelly.com" at -686.44,-1866.06 h72.86
  text "(Bottom)" at 628.11,-1884.03 h72.86
  text "DATE:" at -1601.61,-1984.64 h46.84
  text "ENGINEER:" at -521.96,-1984.64 h46.84
  text "SIZE:" at 208.38,-1984.64 h46.84
  text "REV:" at 684.7,-1984.64 h46.84
  text ".PRINT_DATE" at -1665.12,-2111.66 h72.86
  text "RCA" at -585.47,-2111.66 h72.86
  text "ANSI A" at 144.88,-2111.66 h72.86
  text "'.PCB_Revision'XX" at 621.19,-2111.66 h72.86
  text "4" at -1334.19,-2309.87 h72.9
  text "3" at 1530.61,-2309.87 h72.9
  text "2" at 4389.15,-2309.87 h72.9
  text "1" at 7253.58,-2309.87 h72.9
Doc-Fab:
  lines w5: 8825.96,-2462.5 8825.96,-1406.36 13365.15,-1406.36 ; 8825.96,-1596.36 10585.96,-1596.36 ; 8825.96,-1486.36 10585.96,-1486.36 ; 9245.96,-2462.5 9245.96,-1406.36 ; 10585.96,-2462.5 10585.96,-1406.36 ; 10585.96,-2266.36 13365.96,-2266.36 ; 10585.96,-1826.36 13365.15,-1826.36 ; 11145.96,-2462.5 11145.96,-2266.36 ; 11825.96,-2266.36 11825.96,-1826.36 ; 12475.96,-2462.5 12475.96,-2266.36
  lines w5.49: -2897.87,-74.18 -2678.09,-74.18 ; -2897.87,2535.76 -2678.09,2535.76 ; -2897.87,5145.7 -2678.09,5145.7 ; -150.56,-2684.12 -150.56,-2464.34 ; -150.56,7535.85 -150.56,7755.64 ; 2596.74,-2684.12 2596.74,-2464.34 ; 2596.74,7535.85 2596.74,7755.64 ; 5344.05,-2684.12 5344.05,-2464.34 ; 5344.05,7535.85 5344.05,7755.64 ; 8091.35,-2684.12 8091.35,-2464.34 ; 8091.35,7535.85 8091.35,7755.64 ; 10838.66,-2684.12 10838.66,-2464.34 ; 10838.66,7535.85 10838.66,7755.64 ; 13366.18,-74.18 13585.96,-74.18 ; 13366.18,2535.76 13585.96,2535.76 ; 13366.18,5145.7 13585.96,5145.7 ; -2897.87,-2684.12 13585.96,-2684.12 13585.96,7755.64 -2897.87,7755.64 -2897.87,-2684.12 ; -2678.09,-2464.34 13366.18,-2464.34 13366.18,7535.85 -2678.09,7535.85 -2678.09,-2464.34
  text "1" at -1544.73,7612.78 h76.92
  text "2" at 1197.81,7612.78 h76.92
  text "3" at 3933.41,7612.78 h76.92
  text "4" at 6688.04,7612.78 h76.92
  text "5" at 9434.23,7612.78 h76.92
  text "6" at 12187.03,7612.78 h76.92
  text "A" at -2815.45,6356.71 h76.92
  text "A" at 13448.6,6356.71 h76.92
  text "B" at -2815.45,3741.27 h76.92
  text "B" at 13448.6,3741.27 h76.92
  text "C" at -2815.45,1131.33 h76.92
  text "C" at 13448.6,1131.33 h76.92
  text "REVISION:" at 8854.96,-1466.36 h40
  text "DESCRIPTION:" at 9284.96,-1466.36 h40
  text "D" at -2815.45,-1473.11 h76.92
  text "D" at 13448.6,-1473.11 h76.92
  text "PART NUMBER:" at 10665.96,-1546.36 h75
  text "AXX" at 8855.96,-1566.36 h50
  text "Initial Release" at 9285.96,-1566.36 h50
  text "'.Part_Number'-PCB-'.PCB_Revision'XX" at 10685.96,-1826.36 h130
  text "TITLE:" at 10645.96,-1906.36 h40
  text "Opal Kelly" at 11885.96,-1926.36 h60
  text "13500 SW 72nd Ave Suite 100" at 11885.96,-2026.36 h60
  text "Portland, OR 97223" at 11885.96,-2126.36 h60
  text "'.Part_Number' / Fabrication Drawing" at 10685.96,-2206.36 h60
  text "www.opalkelly.com" at 11885.96,-2226.36 h60
  text "SIZE:" at 10645.96,-2326.36 h40
  text "ENGINEER:" at 11205.96,-2326.36 h40
  text "DATE:" at 12525.96,-2326.36 h40
  text "ANSI A" at 10685.96,-2426.36 h60
  text "RCA" at 11245.96,-2426.36 h60
  text ".PRINT_DATE" at 12565.96,-2426.36 h60
  text "1" at -1544.73,-2607.2 h76.92
  text "2" at 1197.81,-2607.2 h76.92
  text "3" at 3933.41,-2607.2 h76.92
  text "4" at 6688.04,-2607.2 h76.92
  text "5" at 9434.23,-2607.2 h76.92
  text "6" at 12187.03,-2607.2 h76.92

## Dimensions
-0.01,177.16 to 295.27,368.11 on Dimensions
-0.01,177.16 to 590.54,177.16 on Dimensions
590.54,177.16 to 1312.98,177.16 on Dimensions
2249.99,330.71 to 295.27,368.11 on Dimensions
2249.99,330.71 to -0.01,177.16 on Dimensions
2249.99,330.71 to 1771.65,19.68 on Dimensions
2249.99,330.71 to 3791.33,19.68 on Dimensions
2212.59,293.31 to 2287.39,293.31 on Dimensions
1791.33,0 to 2249.99,330.71 on Dimensions
590.54,501.97 to 590.54,177.16 on Dimensions
4638.85,-134.01 to 4687.73,-5.23 on Dimensions
4526.83,-267.19 to 4588.43,-266.84 on Dimensions
4688.68,-266.84 to 4588.43,-321.84 on Dimensions
1627.94,177.16 to 1771.65,19.68 on Dimensions
1312.98,177.16 to 1771.65,19.68 on Dimensions
295.27,368.11 to 295.27,3730.31 on Dimensions
-0.01,4492.13 to 6600.39,4492.13 on Dimensions
-0.01,177.16 to -0.01,4492.13 on Dimensions
1761.8,-9.84 to -0.01,4492.13 on Dimensions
